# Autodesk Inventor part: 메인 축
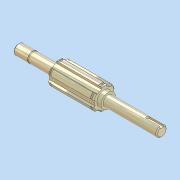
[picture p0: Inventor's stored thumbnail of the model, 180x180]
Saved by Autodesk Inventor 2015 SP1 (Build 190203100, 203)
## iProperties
Created: 2012-05
Part Number: 메인 축
Document SubType Name: 모델링
Designer: SeoGD™
Mass: 21.4461 g
Surface Area: 72.5104 cm^2
Volume: 21.4461 cm^3
Density: 1 g/cm^3
Material: 일반
Appearance: 기본값
변환 표준: STEP AP214IS
파일 이름: C:\Users\SeoGD\Desktop\?쒗뿕\硫붿씤 異?.stp
전처리기: Build: 253, Release: 2010 SP1 - Date: Wed 07/29/2009
전송 단위: 밀리미터
불확실성: 0.01
Author: SeoGD™
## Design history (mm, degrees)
sketch "스케치1"
  geometry: L1 (-69.5, 0)-(69.5, 0); L2 (69.5, 0)-(69.5, 5); L3 (69.5, 5)-(55.5, 5); L4 (55.5, 5)-(55.5, 4.8); L5 (55.5, 4.8)-(54.35, 4.8); L6 (54.35, 4.8)-(54.35, 5); L7 (54.35, 5)-(30.5, 5); L8 (30.5, 5)-(30.5, 9); L9 (30.5, 9)-(-13.5, 9); L10 (-13.5, 9)-(-13.5, 7); L11 (-13.5, 7)-(-17.5, 7); L12 (-17.5, 7)-(-17.5, 5); L13 (-17.5, 5)-(-69.5, 5); L14 (-69.5, 5)-(-69.5, 0); 2 further points
  constraints: 28 end point, 9 parallel, 4 collinear, 2 perpendicular, 1 coincident, 1 horizontal, 1 midpoint
  dimensions: "d2" = 1.15 distance between parallel lines of L6 L4; "d3" = 10 diameter of L3 L1; "d4" = 9.6 diameter of L5 L1; "d6" = 44 distance between parallel lines of L10 L8; "d7" = 4 distance between parallel lines of L12 L10; "d8" = 14 diameter of L11 L1; "d9" = 18 diameter of L9 L1; "d33" = 52 distance from line of L12.end L14; "d37" = 39 distance between parallel lines of L8 L2; "d38" = 14 distance between parallel lines of L2 L4
revolve "회전1" sketch "스케치1" stored, may be unused: angle "d10" = 90 deg
sketch "스케치2"
  geometry: L1 (2.5, 10.712)-(2.5, 8.646); L2 (-2.5, 10.712)-(-2.5, 8.646); A1 r 9 centre (0, 0) between (2.5, 8.646) and (-2.5, 8.646) reference; A2 r 11 centre (0, 0) between (2.5, 10.712) and (-2.5, 10.712); 1 further point
  constraints: 4 end point, 4 point on circle, 2 parallel, 1 centre point, 1 coincident, 1 vertical
  dimensions: "d11" = 22 diameter of A2; "d12" = 5 distance between parallel lines of L1 L2
extrude "돌출1" join sketch "스케치2" stored distance "d13" = 10; taper "d14" = 0 deg
chamfer "모따기1" distance "d15" = 1; stored, may be unused: second distance "d16" = 2, angle "d17" = 45 deg
node "작업 평면1"
node "작업 평면2"
sketch "스케치3"
  geometry: L1 (2.5, 10.712)-(2.5, 10.198); L2 (-2.5, 10.712)-(-2.5, 10.198); A1 r 11 centre (0, 0) between (2.5, 10.712) and (-2.5, 10.712) reference; A2 r 10.5 centre (0, 0) between (2.5, 10.198) and (-2.5, 10.198); 1 further point
  constraints: 4 end point, 2 point on circle, 1 centre point, 1 coincident, 1 parallel, 1 vertical
  dimensions: "d19" = 21 diameter of A2
extrude "돌출2" cut sketch "스케치3" distance "d20" = 1.35; taper "d21" = 0 deg
node "작업 평면3"
sketch "스케치4"
  geometry: L1 (-26, -5)-(-26, 5) reference; L2 (-26, 1.5)-(-12.5, 1.5); L3 (-12.5, -1.5)-(-26, -1.5); A1 r 1.5 centre (-12.5, 0) between (-12.5, -1.5) and (-12.5, 1.5); 2 further points
  constraints: 4 end point, 2 perpendicular, 2 point on circle, 2 point on line, 2 tangent, 1 centre point, 1 horizontal alignment, 1 midpoint
  dimensions: "d25" = 3 distance between parallel lines of L3 L2; "d26" = 15 dimension on A1 L1
extrude "돌출3" cut sketch "스케치4" distance "d27" = 1.8; taper "d28" = 0 deg
chamfer "모따기2" distance "d29" = 1; stored, may be unused: second distance "d30" = 2, angle "d31" = 45 deg
node "솔리드1"
node "솔리드 본체"
node "곡면 본체"
mirror "대칭1"
pattern_circular "원형 패턴1" dims "d23" = 360 deg
node "솔리드2"
other parameters: "d18" = -1.65
